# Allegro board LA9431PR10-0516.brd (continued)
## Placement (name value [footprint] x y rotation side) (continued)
PC927  -  [C_0805]  102.62 69.72 90 bottom
PC928  -  [C_0805]  104.36 66.42 90 bottom
PC929  -  [C_0805]  102.62 73.06 90 bottom
PD1  -  [TVNST52302AB0_SOT523-3]  163.31 7 0 top
PD2  -  [TVNST52302AB0_SOT523-3]  160.45 5.51 180 top
PD3  -  [BAS40-05W_SC70-3]  266.42 58.91 0 top
PD4  -  [RB751V-40_SOD323-2]  157.66 9.1 270 top
PD5  -  [DA204U_SOT323-3]  82.44 94.84 270 top
PD6  -  [D_0603]  82.98 81.05 270 top
PD701  -  [RB717F_SOT323-3]  50 17.96 270 top
PD702  -  [RB751V-40_SOD323-2]  53.55 14.2 0 top
PD800  -  [PDS5100H-13_POWERDI5-3]  81.41 13.11 270 bottom
PD806  -  [PDS5100H-13_POWERDI5-3]  173.07 13.49 180 top
PD807  -  [SDMK0340L-7-F_SOD323-2]  155.31 14.57 270 bottom
PD808  -  [PDS5100H-13_POWERDI5-3]  204.18 10.85 90 bottom
PD810  -  [SDMK0340L-7-F_SOD323-2]  135.12 11.84 270 top
PD811  -  [SDMK0340L-7-F_SOD323-2]  175.11 8.01 90 top
PD813  -  [SDMK0340L-7-F_SOD323-2]  192.77 6.66 270 bottom
PD814  -  [SDMK0340L-7-F_SOD323-2]  133.4 9.56 270 top
PD815  -  [RB717F_SOT323-3]  4.19 37.88 180 top
PD816  -  [SDMK0340L-7-F_SOD323-2]  199.95 12.29 90 top
PD818  -  [SDMK0340L-7-F_SOD323-2]  126.78 7.78 0 top
PD819  -  [SDMK0340L-7-F_SOD323-2]  131.96 12.37 180 top
PD820  -  [SDMK0340L-7-F_SOD323-2]  1.88 36.21 90 top
PD821  -  [SDMK0340L-7-F_SOD323-2]  203.44 10.53 0 top
PH500  -  [R_0402]  84.8 69.62 180 bottom
PH501  -  [R_0402]  93.05 64.78 0 top
PJP1  -  [JUMP_43X118]  87.94 81.56 270 bottom
PJP4  -  [JUMP_43X39]  272.69 45.36 180 bottom
PJP5  -  [JUMP_43X39]  43.99 27.56 90 top
PJP6  -  [JUMP_43X39]  33.21 27.98 180 top
PJP7  -  [JUMP_43X39]  10.02 12.34 90 top
PJP8  -  [JUMP_43X39]  197.85 9.64 270 top
PJP9  -  [JUMP_43X39]  94.87 93 180 top
PJP10  -  [JUMP_43X39]  140.88 101.19 0 top
PJP11  -  [JUMP_43X39]  136.38 91.85 180 top
PJP12  -  [JUMP_43X39]  200.83 74.38 270 bottom
PJP13  -  [JUMP_43X39]  195.33 75.91 270 bottom
PJP14  -  [JUMP_43X39]  206.91 69.91 90 bottom
PJP15  -  [JUMP_43X39]  211.14 70.01 90 bottom
PJP16  -  [JUMP_43X39]  189.37 28.89 90 top
PJP17  -  [JUMP_43X39]  190.44 36.41 270 top
PJP18  -  [JUMP_43X39]  185.03 70.18 270 top
PJP19  -  [JUMP_43X39]  186.89 71.09 0 top
PJP20  -  [JUMP_43X39]  201.1 42.14 0 top
PJP21  -  [JUMP_43X39]  200 34.37 90 top
PJP22  -  [JUMP_43X39]  199.71 29.96 0 top
PJP23  -  [JUMP_43X39]  206.55 25.11 180 top
PJP24  -  [JUMP_43X39]  270.89 21.3 270 top
PJP25  -  [JUMP_43X39]  268.2 15.34 90 top
PJP100  -  [JUMP_43X118-S]  182.61 59.21 0 bottom
PJP101  -  [JUMP_43X118]  185.66 63.11 90 top
PJP102  -  [JUMP_43X118]  196.44 65.25 180 top
PJP200  -  [JUMP_43X79]  108.76 6.68 270 top
PJP201  -  [JUMP_43X39]  111.79 8.25 90 top
PJP202  -  [JUMP_43X39]  112.64 5.36 90 top
PJP203  -  [JUMP_43X118]  90.68 13.5 270 top
PJP204  -  [JUMP_43X118]  95.95 13.5 270 top
PJP300  -  [JUMP_43X79]  223.85 72.24 0 top
PJP301  -  [JUMP_43X79]  223.15 80.05 0 bottom
PJP400  -  [JUMP_43X39]  103.89 96.05 180 bottom
PJP401  -  [JUMP_43X39]  95.94 98.41 270 bottom
PJP402  -  [JUMP_43X39]  101.14 98.37 270 bottom
PJP500  -  [JUMP_43X118-S]  74.79 57.76 0 bottom
PJP700  -  [JUMP_43X118-S]  57.83 11.91 0 bottom
PJP701  -  [JUMP_43X39]  56.67 7.63 90 top
PJPDC1  -  [ACES_50299-00501-003_5P]  91.4 92.8 270 bottom
PL1  -  [TAIYO_FBMJ4516HS720NT_2P]  170.39 6.64 180 top
PL2  -  [TAIYO_FBMJ4516HS720NT_2P]  170.39 9.05 180 top
PL3  -  [MURAT_BLM15AG102SN1D_2P]  88.22 86.36 0 top
PL4  -  [TAIYO_FBMJ4516HS720NT_2P]  82.36 81.43 270 bottom
PL100  -  [CYNTE_PCMB053T-1R0MS_2P]  185.28 59.21 180 bottom
PL101  -  [CYNTE_PCMB064T-3R3MS_2P]  198.79 57.73 90 bottom
PL102  -  [CYNTE_PCMB064T-3R3MS_2P]  191.12 57.77 90 bottom
PL200  -  [CYNTE_PCMB064T-3R3MS_2P]  100.5 12.23 0 bottom
PL300  -  [CYNTE_PCMB064T-3R3MS_2P]  229.71 74.59 180 bottom
PL500  -  [CYNTE_PDME064T-R36MS1R405_4P]  97.05 62.31 180 bottom
PL501  -  [L_1812-1806]  73.44 57.75 0 bottom
PL700  -  [CYNTE_PCMB042T-1R0MS_2P]  59.89 11.85 180 bottom
PL701  -  [TOKO_FDVE1040-H-3R3M-P3_2P]  73.76 10.46 180 bottom
PQ1  -  [FDN338P_NL_SOT23-3]  154.81 6.73 0 top
PQ2  -  [FDV301N_NL_SOT23-3]  83.2 85.95 0 top
PQ3  -  [MMST3904-7-F_SOT323-3]  88.82 90.57 180 top
PQ4  -  [SI7121DN-T1-GE3_POWERPAK8-5]  50.81 37.29 0 bottom
PQ6  -  [IMD2AT-108_SC74-6]  55.14 36.25 0 top
PQ100  -  [SI7326DN-T1-E3_PAK1212-8]  202.67 57.17 180 top
PQ101  -  [SI7326DN-T1-E3_PAK1212-8]  189.1 57.68 180 top
PQ102  -  [SI7326DN-T1-E3_PAK1212-8]  197.5 60.72 270 top
PQ103  -  [SI7326DN-T1-E3_PAK1212-8]  193.49 58.29 90 top
PQ200  -  [SI7326DN-T1-E3_PAK1212-8]  107.07 10.62 270 top
PQ201  -  [SI7326DN-T1-E3_PAK1212-8]  105.56 13.61 180 top
PQ300  -  [SI7326DN-T1-E3_PAK1212-8]  228.94 73.93 180 top
PQ301  -  [SI7326DN-T1-E3_PAK1212-8]  232.18 75.54 90 top
PQ700  -  [SI7121DN-T1-GE3_POWERPAK8-5]  53.24 29.97 180 bottom
PQ701  -  [NTR4502PT1G_SOT23-3]  35.46 9.05 270 top
PQ702  -  [NTR4502PT1G_SOT23-3]  34.76 4.99 270 top
PQ703  -  [NTGD4161PT1G_TSOP6]  43.42 11.18 0 top
PQ704  -  [SIR472DP-T1-GE3_POWERPAK8-5]  66.03 11.02 90 top
PQ706  -  [SIR472DP-T1-GE3_POWERPAK8-5]  62.01 9.3 270 top
PQ710  -  [2N7002DW-T-R7_SOT363-6]  97.85 91.06 270 top
PQ712  -  [2N7002DW-T-R7_SOT363-6]  93.72 90.99 180 top
PQ800  -  [SI4835DDY-T1-GE3_SO8]  84.35 14.64 0 bottom
PQ801  -  [FDN338P_NL_SOT23-3]  152.98 13.25 270 bottom
PQ802  -  [2N7002DW-T-R7_SOT363-6]  129.06 9.36 90 top
PQ805  -  [2N7002DW-T-R7_SOT363-6]  128.86 5.89 270 top
PQ806  -  [2N7002DW-T-R7_SOT363-6]  125.16 9.35 180 top
PQ807  -  [2N7002DW-T-R7_SOT363-6]  148.78 12.13 180 bottom
PQ809  -  [SI4835DDY-T1-GE3_SO8]  171.71 14.83 270 bottom
PQ810  -  [FDS6679AZ-G_SO8]  201.23 9.22 180 bottom
PQ811  -  [FDS6679AZ-G_SO8]  158.95 11.02 90 bottom
PQ812  -  [2N7002DW-T-R7_SOT363-6]  176.96 7.26 0 top
PQ813  -  [2N7002DW-T-R7_SOT363-6]  204.71 5.25 270 bottom
PQ814  -  [FDN338P_NL_SOT23-3]  196.02 5.31 90 bottom
PQ815  -  [FDS6679AZ-G_SO8]  179.15 14.83 270 bottom
PQ816  -  [FDV301N_NL_SOT23-3]  194.64 7.86 180 bottom
PQ817  -  [RHU002N06_SOT323-3]  143.24 11.98 270 top
PQ818  -  [RHU002N06_SOT323-3]  140.11 8.33 270 top
PQ819  -  [2N7002DW-T-R7_SOT363-6]  141.24 4.07 90 top
PQ821  -  [2N7002DW-T-R7_SOT363-6]  202.2 17.26 270 top
PQ822  -  [FDN338P_NL_SOT23-3]  202.15 13.36 270 top
PQ823  -  [FDN338P_NL_SOT23-3]  7.42 38.86 180 top
PQ824  -  [2N7002DW-T-R7_SOT363-6]  7.32 42.09 270 top
PQ825  -  [RHU002N06_SOT323-3]  137.01 4.71 90 top
PQ826  -  [FDMC6679AZ_MLP8-5]  192.15 12.08 90 bottom
PQ827  -  [RHU002N06_SOT323-3]  29.55 42.29 90 bottom
PQ828  -  [RHU002N06_SOT323-3]  205.26 19.21 90 top
PQ829  -  [FDN338P_NL_SOT23-3]  2.17 41.45 270 top
PQ830  -  [FDN338P_NL_SOT23-3]  207.05 8.65 270 top
PQ831  -  [RHU002N06_SOT323-3]  211.42 5.87 180 top
PQ832  -  [RHU002N06_SOT323-3]  2.86 40.11 180 bottom
PR1  -  [R_0402]  266.5 55.08 90 top
PR2  -  [R_0402]  155.99 10.64 0 top
PR6  -  [R0402_0OHM]  154.61 13.39 270 top
PR7  -  [R_0402]  81.75 85.18 180 top
PR8  -  [R_0402]  82.98 92.95 270 top
PR9  -  [R_0402]  82.03 92.04 90 top
PR10  -  [R_0402]  85.64 86.97 270 top
PR11  -  [R_0402]  85.62 88.75 270 top
PR12  -  [R_0402]  86.98 87.97 90 top
PR13  -  [R_0402]  89.45 91.72 180 top
PR14  -  [R_0402]  51.23 40.32 0 top
PR15  -  [R_0402]  53.21 18.97 0 top
PR16  -  [R_0805]  51.63 37.55 270 top
PR17  -  [R_0402]  53.02 40.31 90 top
PR18  -  [R_0402]  51.92 41.21 180 top
PR100  -  [R_0402]  199.7 45.06 180 top
PR101  -  [R_0402]  194.81 44.16 90 top
PR102  -  [R_0402]  199.7 44.17 180 top
PR103  -  [R0402_0OHM]  196.58 45.07 270 top
PR104  -  [R_0402]  195.69 44.16 90 top
PR105  -  [R_0402]  200.2 46.08 0 top
PR106  -  [R_0402]  193.92 45.07 270 top
PR107  -  [R_0402]  200.2 47.85 0 top
PR108  -  [R0402_0OHM]  201.12 46.96 180 top
PR109  -  [R_0603]  192.96 50.33 180 top
PR110  -  [R_0603]  202.04 50.2 180 top
PR111  -  [R_1206]  201.08 62.55 180 top
PR112  -  [R_1206]  190.65 62.59 0 top
PR113  -  [R0402_0OHM]  192.95 47.08 180 top
PR114  -  [R_0402]  192.01 47.98 0 top
PR200  -  [R_0603]  111.43 11.75 270 top
PR201  -  [R_0402]  116.7 14.85 270 top
PR202  -  [R_0603]  117.81 13.65 90 top
PR203  -  [R_1206]  101.14 15.34 0 top
PR204  -  [R_0402]  120.43 12.62 180 top
PR205  -  [R_0402]  120.41 6.36 180 top
PR206  -  [R_0402]  120.43 11.73 180 top
PR207  -  [R_0402]  120.43 10.85 180 top
PR208  -  [R0402_0OHM]  120.43 9.96 180 top
PR209  -  [R_0402]  120.4 4.61 180 top
PR210  -  [R0402_0OHM]  120.43 8.18 180 top
PR211  -  [R_0402]  120.43 7.29 180 top
PR300  -  [R_0402]  237.91 71.48 0 top
PR301  -  [R_0603]  236.02 71.09 180 top
PR302  -  [R_0402]  240.86 71.67 180 top
PR303  -  [R_0402]  240.86 72.55 180 top
PR304  -  [R0402_0OHM]  240.86 73.44 180 top
PR305  -  [R_0402]  238.76 76.75 180 top
PR306  -  [R_1206]  231.83 79.32 0 top
PR307  -  [R_0402]  240.86 75.22 180 top
PR308  -  [R_0402]  240.86 76.11 180 top
PR400  -  [R_0402]  103.62 94.54 270 bottom
PR401  -  [R_0402]  103.58 91.85 90 bottom
PR402  -  [R_0402]  94.36 93.85 270 bottom
PR403  -  [R_0402]  93.48 92.06 0 bottom
PR500  -  [R_0402]  91.57 69.71 270 top
PR501  -  [R_0402]  89.13 69.57 0 bottom
PR502  -  [R_0402]  88.77 69.71 270 top
PR503  -  [R_0402]  87.88 69.71 270 top
PR504  -  [R_0402]  87 69.71 270 top
PR505  -  [R_0402]  89.7 68.81 0 top
PR506  -  [R_0402]  90.23 72.06 270 bottom
PR507  -  [R_0402]  89.34 72.06 270 bottom
PR508  -  [R_0402]  88.46 72.06 270 bottom
PR509  -  [R_0402]  87.57 72.06 270 bottom
PR510  -  [R_0402]  92.39 72 270 bottom
PR511  -  [R_0402]  92.46 68.8 90 top
PR512  -  [R_0402]  92.19 63.93 270 top
PR513  -  [R_0402]  87.55 73.7 0 bottom
PR514  -  [R_0402]  93.08 63.93 270 top
PR515  -  [R_0402]  93.97 63.93 270 top
PR516  -  [R_0402]  85.86 75.41 180 top
PR517  -  [R_0603]  79.27 66.76 180 bottom
PR519  -  [R_0603]  84.44 76.48 0 top
PR520  -  [R0402_0OHM]  84.95 72.62 0 top
PR521  -  [R_0402]  91.33 77.57 180 top
PR522  -  [R_1206]  85.61 63.18 270 bottom
PR523  -  [R_0402]  93.1 78.46 180 top
PR526  -  [R_0603]  89.9 78.65 0 top
PR527  -  [R_0402]  88.07 78.66 270 top
PR528  -  [R_0402]  87.19 78.66 270 top
PR529  -  [R_0402]  86.3 78.66 270 top
PR531  -  [R0402_0OHM]  93.37 75.35 90 top
PR532  -  [R0402_0OHM]  94.26 75.35 90 top
PR534  -  [R0402_0OHM]  88.96 77.74 90 top
PR535  -  [R_0402]  93.14 79.46 90 top
PR536  -  [R0402_0OHM]  84.95 71.73 0 top
PR537  -  [R_0402]  84.94 70.85 0 top
PR539  -  [R0402_0OHM]  84.95 74.52 0 top
PR540  -  [R_0402]  84.95 73.63 0 top
PR700  -  [R_1206_4P-D]  52.96 23.7 90 bottom
PR701  -  [R0402_0OHM]  49.99 29.12 90 bottom
PR702  -  [R0402_0OHM]  39.32 5.64 270 top
PR703  -  [R_0402]  45.62 8.7 270 top
PR704  -  [R_0402]  46.48 7.8 0 top
PR705  -  [R_0402]  46.48 8.69 0 top
PR706  -  [R_0402]  41.1 5.57 180 top
PR707  -  [R_0402]  44.49 9.75 0 top
PR708  -  [R_0805]  46.95 15.72 0 top
PR709  -  [R0402_0OHM]  41.1 4.58 180 top
PR710  -  [R0402_0OHM]  43.63 3.83 180 top
PR711  -  [R_0402]  54.75 15.44 90 top
PR713  -  [R_0402]  49.7 4.84 270 top
PR714  -  [R_0402]  51.42 4.81 270 top
PR715  -  [R_0603]  53.63 11.45 90 top
PR716  -  [R_1206_4P-D]  77.74 15.3 270 bottom
PR717  -  [R0402_0OHM]  47.54 3.47 0 top
PR718  -  [R0402_0OHM]  58.73 4.89 270 top
PR719  -  [R0402_0OHM]  57.81 4.86 270 top
PR722  -  [R_0402]  56.91 3.94 90 top
PR724  -  [R_1206]  60.2 6.31 270 top
PR725  -  [R0402_0OHM]  47.61 4.55 90 top
PR726  -  [R_0402]  55.82 3.91 180 top
PR727  -  [R_0402]  92.37 83.76 270 top
PR728  -  [R0402_0OHM]  100.93 91.3 0 top
PR729  -  [R_0402]  93.38 85.67 90 top
PR730  -  [R_0402]  95.12 88.56 270 top
PR732  -  [R_0402]  97.47 85.65 180 top
PR734  -  [R_0402]  94.26 87.48 180 top
PR735  -  [R_0402]  95.19 86.61 270 top
PR736  -  [R_0402]  95.06 83.74 270 top
PR737  -  [R_0402]  95.91 81.9 0 top
PR738  -  [R_0402]  96.01 80.59 90 bottom
PR739  -  [R_0402]  95.12 80.59 90 bottom
PR740  -  [R_0402]  99.73 88.72 270 top
PR741  -  [R0402_0OHM]  94.23 81.51 270 bottom
PR742  -  [R_0402]  95.94 82.83 90 top
PR743  -  [R_0402]  97.79 81.51 270 bottom
PR744  -  [R_0402]  93.35 81.51 270 bottom
PR745  -  [R_1206]  48.31 13.37 0 top
PR746  -  [R_0402]  50.32 6.12 0 bottom
PR747  -  [R_0402]  48.5 5.44 270 top
PR748  -  [R_0402]  41.97 7.14 0 top
PR749  -  [R_0402]  41.07 6.49 90 top
PR750  -  [R0402_0OHM]  55.82 4.8 180 top
PR751  -  [R_0402]  53.16 3.68 0 top
PR801  -  [R_0402]  127.18 4.98 90 top
PR802  -  [R_0402]  151.87 10.77 0 bottom
PR804  -  [R_0402]  150.94 10.77 180 bottom
PR807  -  [R_0402]  132.04 6.98 180 top
PR808  -  [R_0402]  147.23 10.71 0 bottom
PR810  -  [R_0402]  122.73 9.23 90 top
PR811  -  [R0402_0OHM]  197.03 7.73 0 bottom
PR812  -  [R0402_0OHM]  122.73 11.99 270 top
PR813  -  [R_0402]  177.5 11.68 90 top
PR814  -  [R_0402]  198.63 15.02 270 top
PR815  -  [R_0402]  177.51 10.77 180 top
PR816  -  [R_0402]  178.61 5.92 180 top
PR817  -  [R_0402]  167.18 14.05 90 top
PR818  -  [R_0402]  193.12 10.49 180 top
PR819  -  [R_0402]  143.09 10.27 270 top
PR820  -  [R0402_0OHM]  138.52 12.61 0 top
PR821  -  [R_0603]  156.77 13.37 90 bottom
PR822  -  [R_0402]  193.12 9.61 180 top
PR823  -  [R_0402]  138.86 8.29 270 top
PR824  -  [R_0402]  141.52 6.59 180 top
PR825  -  [R0402_0OHM]  138.13 9.23 0 top
PR826  -  [R_0402]  199.81 5.93 0 bottom
PR827  -  [R_0402]  199.82 4.78 270 bottom
PR828  -  [R_0402]  2.41 42.8 0 bottom
PR829  -  [R_0402]  209.6 2.82 180 top
PR830  -  [R_0402]  5.44 40.94 180 bottom
PR831  -  [R0402_0OHM]  1.44 27.09 0 top
PR832  -  [R0402_0OHM]  1.44 27.98 0 top
PR833  -  [R0402_0OHM]  1.44 25.5 0 top
PR834  -  [R0402_0OHM]  147.87 14.13 0 top
PR835  -  [R_0805]  2.6 21.45 90 top
PR836  -  [R_0402]  208.13 11.07 0 top
PR837  -  [R_0402]  211.76 7.04 180 top
PR838  -  [R0402_0OHM]  2.25 31.28 270 top
PR839  -  [R_0402]  205.98 13.06 270 top
PR840  -  [R_0402]  205.98 13.98 90 top
PR841  -  [R0402_0OHM]  1.44 29.25 0 top
PR843  -  [R0402_0OHM]  2.86 32.61 180 top
PR844  -  [R_0402]  4.52 38.96 180 top
PR846  -  [R_0402]  10.15 22.85 270 top
PR847  -  [R0402_0OHM]  6.4 22.19 90 top
PR848  -  [R_0402]  200.71 3.77 90 bottom
PR849  -  [R_0402]  179.93 5.88 0 top
PR850  -  [R0402_0OHM]  2.86 33.5 180 top
PR851  -  [R_0402]  206.17 16.74 180 top
PR852  -  [R0402_0OHM]  146.37 11.29 0 top
PR853  -  [R0402_0OHM]  201.6 3.76 90 bottom
PR854  -  [R0402_0OHM]  7.29 22.19 90 top
PR855  -  [R0402_0OHM]  5.19 33.24 90 top
PR856  -  [R_0402]  28.37 41.13 90 bottom
PR857  -  [R0402_0OHM]  6.97 33.24 90 top
PR858  -  [R_0402]  6.08 34.15 270 top
PR859  -  [R0402_0OHM]  8.18 22.19 90 top
PR860  -  [R0402_0OHM]  7.85 33.13 90 top
PR861  -  [R0402_0OHM]  202.53 19.14 90 top
PR862  -  [R0402_0OHM]  9.07 22.19 90 top
PR863  -  [R0402_0OHM]  8.74 33.13 90 top
PR864  -  [R_0402]  138.15 6.52 270 top
PR866  -  [R0402_0OHM]  12.76 29.76 180 top
PR868  -  [R0402_0OHM]  11.85 30.64 0 top
PR869  -  [R_0402]  8.89 35.03 180 top
PR870  -  [R_0402]  6.46 41.87 90 bottom
PR872  -  [R0402_0OHM]  133.83 4.15 90 top
PR874  -  [R_0402]  11.85 28.87 0 top
PR875  -  [R_0402]  10.38 42.75 270 top
PR877  -  [R0402_0OHM]  11.85 27.98 0 top
PR894  -  [R_0402]  4.92 40.04 0 bottom
PR895  -  [R0402_0OHM]  4.52 41.83 0 bottom
PRP2  -  [RP_0804_8P4R]  160.16 12.66 270 top
PU2  -  [LM393DR_SO8]  93.73 88.71 0 bottom
PU3  -  [TC7SH08FU_SSOP5]  102.99 88.97 90 top
PU11  -  [RT8207MZQW_WQFN20_3X3]  115.01 8.89 0 top
PU100  -  [TPS51225CRUKR_QFN20_3X3]  196.04 47.7 0 top
PU111  -  [TS5A63157DCKR_SC70-6]  79.6 93.97 0 top
PU300  -  [TPS51218DSCR_SON10_3X3]  238.62 73.08 90 top
PU400  -  [APL5915KAI-TRL_SO8]  95.96 92.13 90 bottom
PU500  -  [TPS51622RSM_QFN32_4X4]  87.81 74.84 270 top
PU501  -  [CSD97374CQ4M_SON8_3P5X4P5-S]  84.22 67.92 270 bottom
PU700  -  [BQ24715RGRR_QFN20_3P5X3P5]  50.84 8.91 270 top
PU703  -  [INA199A2DCKR_SC70-6]  45.17 4.82 90 top
PU800  -  [CD3301RHHR_QFN36_6X6]  4.78 25.2 0 top
PU801  -  [TC7SH08FU_SSOP5]  131.9 10.89 180 top
PU804  -  [TC7SH08FU_SSOP5]  123.82 12.18 270 top
PU805  -  [TC7SH08FU_SSOP5]  141.72 12.16 180 top
PU806  -  [TC7SH08FU_SSOP5]  139.23 10.31 90 top
PU807  -  [TC7SH08FU_SSOP5]  136.97 6.63 90 top
PU808  -  [TC7SH08FU_SSOP5]  209.6 5.93 180 top
Q1  -  [LP2301ALT1G_SOT23-3]  142.84 103.35 270 top
Q2  -  [FDC654P-G_SSOT-6]  65.52 68.9 0 bottom
Q3  -  [LP2301ALT1G_SOT23-3]  91.77 94.4 90 top
Q4  -  [L2N7002WT1G_SC-70-3]  72.38 68.81 0 top
Q5  -  [DMN66D0LDW-7_SOT363-6]  33.5 24.34 180 top
Q6  -  [BSS138W-7-F_SOT323-3]  179.76 89.45 270 bottom
Q7  -  [L2N7002WT1G_SC-70-3]  53.77 77.12 0 top
Q9  -  [L2N7002WT1G_SC-70-3]  13.07 21.5 180 top
Q10  -  [BSS138W-7-F_SOT323-3]  210.74 88.5 0 bottom
Q11  -  [MMBT3904WT1G_SC70-3]  131.57 70.77 0 top
Q12  -  [MMST3904-7-F_SOT323-3]  33.96 20.36 270 top
Q13  -  [MMBT3904WT1G_SC70-3]  126.02 18.54 0 top
Q14  -  [MMBT3904WT1G_SC70-3]  97.01 56.55 270 bottom
Q15  -  [PDTA114EU_SC70-3]  204.11 93.52 90 bottom
Q16  -  [PDTA114EU_SC70-3]  204.11 95.94 90 bottom
Q17  -  [DMN66D0LDW-7_SOT363-6]  148.19 99.48 90 top
Q20  -  [DMN66D0LDW-7_SOT363-6]  278.51 26.65 180 top
Q21  -  [DMN66D0LDW-7_SOT363-6]  281.75 24.27 90 top
Q22  -  [DMN66D0LDW-7_SOT363-6]  208.09 27.23 270 top
Q23  -  [DMN66D0LDW-7_SOT363-6]  110.97 109.26 0 top
Q24  -  [DMN66D0LDW-7_SOT363-6]  199.1 93.32 0 top
Q25  -  [DMN66D0LDW-7_SOT363-6]  200.22 93.32 180 bottom
Q26  -  [PDTA114EU_SC70-3]  195.97 91.73 270 bottom
Q28  -  [DMN66D0LDW-7_SOT363-6]  231.3 108.11 0 bottom
Q29  -  [L2N7002WT1G_SC-70-3]  187.96 97.09 270 top
Q30  -  [DMN66D0LDW-7_SOT363-6]  205.84 40.87 0 top
Q31  -  [BSS138W-7-F_SOT323-3]  231.57 89.7 270 bottom
Q32  -  [DMN66D0LDW-7_SOT363-6]  232.32 94.93 180 top
Q33  -  [DMN66D0LDW-7_SOT363-6]  234.76 96.15 180 top
Q120  -  [DMN66D0LDW-7_SOT363-6]  203.24 99.94 270 bottom
Q121  -  [L2N7002WT1G_SC-70-3]  202.23 97.19 270 top
Q123  -  [DMN66D0LDW-7_SOT363-6]  267.56 24.36 0 top
Q124  -  [DMN66D0LDW-7_SOT363-6]  160.04 92.03 180 top
Q125  -  [SI3456DDV-T1-GE3_TSOP6]  151.04 91.77 90 top
QC1  -  [DMN66D0LDW-7_SOT363-6]  163.23 70.46 0 top
QD1  -  [BSS138-G_SOT23-3]  121.62 31.88 90 top
R1  -  [R_0402]  168.92 74.04 270 bottom
R2  -  [R_0402]  174.28 74.03 270 bottom
R3  -  [R_0402]  170.31 82.84 180 bottom
R4  -  [R_0402]  163.69 83.27 90 bottom
R5  -  [R_0402]  176.1 75.96 270 bottom
R6  -  [R_0402]  169.79 73.11 90 bottom
R7  -  [R_0402]  179.25 79.11 270 bottom
R8  -  [R_0402]  166.12 75.03 180 bottom
R9  -  [R_0402]  176.19 81.99 270 bottom
R10  -  [R_0402]  170.6 81.72 0 bottom
R11  -  [R_0402]  175.22 82.65 270 bottom
R12  -  [R_0402]  174.37 81.76 180 bottom
R13  -  [R_0402]  177.41 78.19 90 bottom
R14  -  [R_0402]  164.52 68.69 270 bottom
R15  -  [R_0402]  165.2 72.75 0 bottom
R16  -  [R_0402]  175.23 73.1 90 bottom
R17  -  [R_0402]  164.5 69.63 0 bottom
R18  -  [R_0402]  178.3 78.19 90 bottom
R19  -  [R_0402]  166.94 74.04 0 bottom
R20  -  [R_0402]  179.25 76.42 90 bottom
R21  -  [R_0402]  176.19 79.31 90 bottom
R22  -  [R_0402]  164.64 82.92 0 bottom
R23  -  [R_0402]  167.86 73.15 180 bottom
R24  -  [R_0402]  110.99 91.05 270 bottom
R25  -  [R_0402]  247.75 71.97 270 top
R26  -  [R_0402]  194.6 40.4 0 top
R27  -  [R_0402]  250.43 28.66 90 top
R28  -  [R_0402]  127.75 28.52 90 top
R29  -  [R_0402]  99.2 19.98 180 top
R30  -  [R_0402]  99.2 19.09 180 top
R31  -  [R_0402]  176.31 17.81 270 top
R32  -  [R_0402]  128.64 28.54 90 top
R33  -  [R_0402]  177.45 17.81 270 top
R35  -  [R_0402]  31.1 24.43 270 top
R36  -  [R_0402]  34.53 23.29 270 top
R37  -  [R0402_0OHM]  252.4 9.13 270 top
R38  -  [R_0402]  254.47 9.09 270 top
R39  -  [R_0402]  279.88 33.25 0 top
R40  -  [R_0402]  194.11 88.67 90 top
R41  -  [R_0402]  164.64 82.02 0 bottom
R42  -  [R_0402]  195.95 88.67 90 top
R43  -  [R_0402]  173.38 74.03 270 bottom
R44  -  [R_0402]  203.48 78.14 0 top
R45  -  [R_0402]  179.25 74.64 90 bottom
R46  -  [R_0402]  200.65 89.12 90 top
R47  -  [R_0402]  203.48 79.03 0 top
R48  -  [R_0402]  172.49 74.03 270 bottom
R49  -  [R_0402]  201.54 89.12 90 top
R50  -  [R_0402]  29.54 38.52 180 top
R51  -  [R_0402]  14.38 25.39 90 top
R52  -  [R_0402]  187.96 87.79 180 top
R53  -  [R_0402]  202.92 74.46 0 top
R54  -  [R_0402]  203.48 75.35 0 top
R56  -  [R_0402]  180.33 81.71 270 bottom
R57  -  [R_0402]  178.22 82.59 0 bottom
R58  -  [R_0402]  171.55 74.03 270 bottom
R59  -  [R_0402]  170.66 74.03 270 bottom
R60  -  [R_0402]  210.68 85.31 90 bottom
R63  -  [R_0402]  189.15 73.3 90 top
R64  -  [R_0402]  192.68 86.64 0 bottom
R65  -  [R_0402]  191.87 78.33 0 bottom
R66  -  [R_0402]  187.06 76.12 270 top
R67  -  [R_0402]  236.91 90.28 270 top
R69  -  [R_0402]  191.31 88.73 90 top
R70  -  [R_0402]  203.49 77.18 0 top
R72  -  [R_0402]  203.49 76.29 0 top
R73  -  [R0402_0OHM]  212.1 81.88 90 top
R74  -  [R_0402]  190.09 73.25 0 top
R75  -  [R0402_0OHM]  210.25 81.85 90 top
R76  -  [R0402_0OHM]  209.36 78.4 90 top
R77  -  [R0402_0OHM]  213.91 79.98 0 top
R81  -  [R0402_0OHM]  213.91 80.87 0 top
R84  -  [R0402_0OHM]  207.56 78.36 90 top
R85  -  [R_0402]  193.95 74.38 270 top
R88  -  [R0402_0OHM]  206.67 78.36 90 top
R91  -  [R_0402]  198.62 89.18 90 top
R92  -  [R_0402]  199.63 89.18 90 top
R94  -  [R_0402]  146.67 102.73 270 top
R95  -  [R_0402]  59.18 79.48 180 top
R96  -  [R_0402]  58.9 83.79 0 top
R97  -  [R_0402]  70.61 67.86 180 top
R99  -  [R_0402]  69.7 68.81 0 top
R100  -  [R_0402-S]  68.16 70.91 110 bottom
R101  -  [R_0402-S]  69.26 71.27 110 bottom
R102  -  [R_0402]  81.97 96.11 90 top
R104  -  [R_0402]  54.76 68.17 90 top
R106  -  [R0402_0OHM]  83.79 96.75 180 top
R107  -  [R0402_0OHM]  187.12 78.03 270 top
R108  -  [R_0402]  66.29 73.74 0 bottom
R120  -  [R_0402]  114.86 109.09 270 top
R121  -  [R_0402]  113.27 95.08 90 bottom
R122  -  [R_0402]  125.78 27.9 90 top
R123  -  [R_0402]  124.89 27.9 90 top
R129  -  [R0402_0OHM]  203.15 22.54 90 top
R130  -  [R0805_0OHM]  266.6 40.13 270 top
R131  -  [R0402_0OHM]  190.32 41.31 270 top
R136  -  [R_0402]  274.13 27.61 90 top
R137  -  [R_0402]  280.8 29.69 180 top
R139  -  [R_0402]  280.8 30.58 180 top
R140  -  [R0603_0OHM]  269.8 15.15 0 top
R142  -  [R_0402]  280.8 31.47 180 top
R143  -  [R0402_0OHM]  280.8 32.36 180 top
R144  -  [R0402_0OHM]  278.64 40.21 270 top
R145  -  [R0402_0OHM]  242.43 74.09 0 top
R147  -  [R_0402]  274.22 23.42 180 top
R148  -  [R_0402]  272.3 28.51 270 top
R149  -  [R_0402]  273.25 28.51 270 top
R150  -  [R_0402]  266.9 29.69 0 top
R151  -  [R_0402]  274.22 24.32 180 top
R152  -  [R_0402]  277.8 28.63 270 top
R153  -  [R_0402]  275.2 26.01 0 top
R154  -  [R0402_0OHM]  266.19 22.4 270 top
R155  -  [R_0402]  45.57 29.51 270 top
R156  -  [R_0402]  278.69 28.63 270 top
R157  -  [R_0402]  279.88 28.74 0 top
R158  -  [R_0402]  282.37 21.5 90 top
R159  -  [R_0402]  281.47 21.5 90 top
R160  -  [R_0402]  155.68 76.83 180 bottom
R161  -  [R_0402]  168 82.84 0 top
R162  -  [R_0402]  272.44 39.71 90 top
R163  -  [R_0402]  237.68 85.89 180 top
R164  -  [R_0402]  166.87 89.12 90 bottom
R165  -  [R_0402]  237.68 87.86 180 top
R166  -  [R_0402]  273.33 39.71 90 top
R167  -  [R_0402]  237.8 89.37 90 top
R168  -  [R_0402]  271.62 88.61 90 top
R169  -  [R0402_0OHM]  256.79 73.13 180 top
R170  -  [R_0402]  270.52 28.57 270 top
R171  -  [R_0402]  245.97 76.24 0 top
R172  -  [R_0402]  245.97 75.29 0 top
R173  -  [R_0402]  261.86 72.31 270 top
R174  -  [R0402_0OHM]  245.97 78.97 0 top
R175  -  [R0402_0OHM]  259.21 76.24 180 top
R176  -  [R_0402]  258.29 74.4 0 top
R177  -  [R0402_0OHM]  245.97 77.19 0 top
R178  -  [R_0402]  259.21 73.51 180 top
R179  -  [R0402_0OHM]  259.21 75.29 180 top
R180  -  [R0402_0OHM]  263.83 71.4 90 top
R181  -  [R0603_0OHM]  259.77 83.16 270 top
R182  -  [R_0402]  262.88 71.4 90 top
R183  -  [R0402_0OHM]  258.31 77.11 90 top
R184  -  [R_0402]  246.89 78.08 180 top
R185  -  [R_0402]  258.29 80.75 0 top
R186  -  [R_0402]  267.2 32.19 180 top
R187  -  [R_0402]  276.36 39.17 90 top
R190  -  [R_0402]  181.79 7.99 0 top
R191  -  [R_0402]  181.79 8.88 0 top
R193  -  [R0402_0OHM]  35.24 39.33 270 top
R194  -  [R_0402]  275.2 23.28 0 top
R195  -  [R_0402]  189.98 9 270 top
R196  -  [R0402_0OHM]  198.12 38.58 180 top
R197  -  [R_0402]  276.14 40.93 0 top
R198  -  [R_0402]  108.36 83.63 90 bottom
R202  -  [R_0402]  268.39 27.56 180 top
R205  -  [R_0402]  260.4 26.15 270 top
R206  -  [R_0402]  258.31 78.89 90 top
R207  -  [R_0402]  193.15 89.65 270 top
R211  -  [R_0402]  254.5 15.52 270 top
R212  -  [R_0402]  251.8 20.14 0 top
R213  -  [R_0402]  267.78 22.91 0 top
R214  -  [R_0402]  252.72 21.03 180 top
R215  -  [R_0402]  209.26 18.12 90 top
R216  -  [R_0402]  205.68 48.22 0 top
R217  -  [R_0402]  205.68 50.89 0 top
R218  -  [R_0402]  206.59 49.11 180 top
R219  -  [R_0402]  206.59 50 180 top
R220  -  [R0402_0OHM]  267.78 22.01 0 top
R222  -  [R_0402]  209.27 13.63 0 top
R223  -  [R0402_0OHM]  208.36 29.46 0 bottom
R224  -  [R_0402]  209.83 23.7 90 top
R225  -  [R_0402]  207.95 28.94 0 top
R226  -  [R_0402]  206.9 44.84 270 top
R227  -  [R_0402]  207.14 27.56 270 top
R228  -  [R_0402]  211.09 26.01 90 top
R229  -  [R_0402]  205.63 39.7 0 top
R230  -  [R_0402]  263.37 20.74 0 top
R231  -  [R0402_0OHM]  269.11 13.03 270 top
R235  -  [R_0402-S]  205.02 95.61 0 top
R236  -  [R_0402-S]  205.02 94.4 0 top
R237  -  [R_0402-S]  205.02 93.45 0 top
R238  -  [R_0402-S]  202.67 90.53 0 bottom
R239  -  [R_0402-S]  205.02 92.3 0 top
R240  -  [R_0402-S]  202.67 89.64 0 bottom
R241  -  [R0402_0OHM]  54.04 74.08 180 top
R242  -  [R0402_0OHM]  49.66 73.23 90 top
R243  -  [R_0402]  53.76 78.33 0 top
R244  -  [R_0402]  71.49 87.55 270 top
R246  -  [R_0402-S]  75.93 89.12 90 top
R247  -  [R_0402-S]  77.08 89.12 90 top
R248  -  [R_0402-S]  77.97 89.12 90 top
R249  -  [R_0402-S]  73.14 89.12 90 top
R250  -  [R_0402-S]  79.17 89.12 90 top
R251  -  [R_0402-S]  74.28 89.12 90 top
R252  -  [R_0402]  115.1 95.12 90 bottom
R253  -  [R_0402]  115.99 95.12 90 bottom
R254  -  [R_0402]  115.99 96.03 270 top
R255  -  [R_0402]  116.88 95.12 90 bottom
R256  -  [R_0402]  116.88 96.03 270 top
R257  -  [R_0402]  117.77 95.12 90 bottom
R258  -  [R_0402]  119.54 96.03 270 top
R259  -  [R_0402]  114.21 95.12 90 bottom
R260  -  [R_0402]  114.21 96.03 270 top
R261  -  [R_0402]  115.1 96.03 270 top
R262  -  [R_0402]  117.77 96.03 270 top
R263  -  [R_0402]  118.66 95.12 90 bottom
R264  -  [R_0402]  118.66 96.03 270 top
R265  -  [R_0402]  119.54 95.12 90 bottom
R266  -  [R_0402]  120.43 95.12 90 bottom
R267  -  [R_0402]  120.43 96.03 270 top
R268  -  [R_0402]  123.74 96.92 270 bottom
R269  -  [R0402_0OHM]  124.58 95.62 0 top
R270  -  [R0402_0OHM]  124.58 96.63 0 top
R271  -  [R_0402]  123.38 108.11 180 top
R272  -  [R_0402]  147.96 109 180 top
R273  -  [R_0402]  145.39 97.19 0 bottom
R274  -  [R_0402]  243.12 94.72 0 top
R275  -  [R_0402]  261.54 88.85 90 top
R276  -  [R_0402]  262.5 88.85 90 top
R277  -  [R_0402]  248.37 94.39 270 top
R278  -  [R_0402]  249.64 94.39 270 top
R279  -  [R_0402]  256.03 94.32 270 top
R280  -  [R_0402]  257.3 94.32 270 top
R281  -  [R_0402]  17.45 42.66 270 top
R282  -  [R_0402]  25.26 42.91 270 top
R284  -  [R_0402]  17.39 26.25 90 top
R285  -  [R_0402]  25.26 42 90 bottom
R287  -  [R_0402]  15.55 26.25 90 top
R288  -  [R_0402]  23.99 42.91 270 top
R289  -  [R_0402]  16.43 26.25 90 top
R291  -  [R_0402]  15.46 42.46 270 bottom
R292  -  [R_0402]  10.01 37.01 270 top
R293  -  [R_0402]  29.46 27.34 180 top
R295  -  [R_0402]  19.74 42.66 270 top
R296  -  [R_0402]  29.46 33.76 180 top
R297  -  [R0402_0OHM]  267.97 13.03 270 top
R298  -  [R_0402]  22.28 26.25 90 top
R299  -  [R_0402]  29.46 31.98 180 top
R300  -  [R_0402]  29.46 32.87 180 top
R301  -  [R_0402]  32.74 30.26 0 top
R303  -  [R_0402]  21.32 26.25 90 top
R304  -  [R_0402]  23.23 26.25 90 top
R305  -  [R_0402]  29.46 29.18 180 top
R306  -  [R0402_0OHM]  261.25 11.67 0 top
R307  -  [R_0402]  29.53 37.57 180 top
R309  -  [R_0402]  22.47 42.72 270 top
R310  -  [R_0402]  17.41 42.49 270 bottom
R311  -  [R_0402]  212.09 83.72 0 top
R312  -  [R_0402]  210.24 83.72 0 top
R313  -  [R_0402]  18.34 42.66 270 top
R315  -  [R0402_0OHM]  261.25 10.53 0 top
R317  -  [R_0402]  10.06 34.96 0 top
R319  -  [R0402_0OHM]  29.46 28.3 180 top
R320  -  [R_0402]  10.97 34.06 180 top
R321  -  [R_0402]  28.55 30.96 0 top
R322  -  [R_0402]  10.87 39.62 180 top
R324  -  [R_0402]  28.61 36.55 0 top
R325  -  [R_0402]  11.99 40.22 270 top
R326  -  [R_0402]  19.93 27.16 270 top
R327  -  [R_0402]  13.28 5.31 0 top
R328  -  [R_0402]  11.81 5.31 180 top
R329  -  [R_0402]  14.2 6.26 180 top
R330  -  [R_0402]  14.48 3.47 180 top
R331  -  [R_0402]  244.02 71.59 90 top
R332  -  [R0402_0OHM]  13.63 15.21 0 top
R333  -  [R0402_0OHM]  261.25 8.43 0 top
R334  -  [R0402_0OHM]  14.22 20.36 180 top
R335  -  [R_0402]  15.8 23.1 270 top
R336  -  [R0402_0OHM]  33.96 12.41 90 top
R337  -  [R0402_0OHM]  261.25 9.58 0 top
R338  -  [R_0402]  32.51 6.91 180 top
R339  -  [R_0402]  16.42 15.67 0 top
R340  -  [R_0402]  35.48 24.47 90 top
R341  -  [R0402_0OHM]  263.37 23.6 0 top
R342  -  [R_0402]  14.85 23.1 270 top
R343  -  [R_0402]  23.29 24.31 270 top
R344  -  [R_0402]  35.74 13.32 270 top
R345  -  [R_0402]  13.63 17.12 0 top
R346  -  [R_0402]  15.53 7.98 0 top
R347  -  [R_0402]  15.53 8.86 0 top
R348  -  [R_0402]  21.13 23.1 270 top
R349  -  [R_0402]  11 20.22 270 top
R350  -  [R_0402]  34.53 24.47 90 top
R351  -  [R_0402]  209.35 80.34 180 top
R352  -  [R_0402]  15.8 4.37 270 top
R353  -  [R_0402]  28.69 23.16 270 top
R354  -  [R_0402]  26.85 23.16 270 top
R355  -  [R_0402]  37.45 23.29 270 top
R356  -  [R_0402]  25.96 23.16 270 top
R357  -  [R_0402]  36.5 23.29 270 top
R358  -  [R_0402]  16.69 4.37 270 top
R359  -  [R_0402]  20.94 6.37 90 top
R360  -  [R_0402]  13.56 18.2 0 top
R361  -  [R_0402]  20.05 4.75 270 top
R362  -  [R_0402]  32.51 6.03 180 top
R363  -  [R_0402]  27.8 23.16 270 top
R364  -  [R_0402]  21.01 4.75 270 top
R365  -  [R_0402]  19.99 6.37 90 top
R366  -  [R_0402]  25.07 23.16 270 top
R367  -  [R_0402]  16.69 22.19 90 top
R368  -  [R_0402]  32.89 14.2 180 top
R369  -  [R_0402]  32.89 11.53 180 top
R370  -  [R_0402]  17.58 22.19 90 top
R371  -  [R_0402]  32.89 15.09 180 top
R372  -  [R_0402]  34.26 14.2 0 top
R373  -  [R_0402]  39.29 23.29 270 top
R374  -  [R0402_0OHM]  19.37 23.09 180 top
R375  -  [R_0402]  20.24 22.19 90 top
R376  -  [R_0402]  36.75 12.41 90 top
R377  -  [R_0402]  38.34 23.29 270 top
R378  -  [R0402_0OHM]  16.43 10.01 90 top
R379  -  [R0402_0OHM]  13.63 16.17 0 top
R380  -  [R_0402]  11.09 18.45 0 top
R381  -  [R_0402]  17.34 12.69 180 top
R382  -  [R_0402]  31.99 17.27 0 top
R383  -  [R_0402]  35.18 15.98 180 top
R384  -  [R_0402]  12 17.5 180 top
R385  -  [R_0402]  6.96 7.57 90 top
R386  -  [R_0402]  23.86 4.75 270 top
R387  -  [R_0402]  31.6 5.14 0 top
R388  -  [R_0402]  5.88 7.57 90 top
R391  -  [R_0402]  7.98 7.57 90 top
R392  -  [R_0402]  25.91 3.91 180 top
R393  -  [R_0402]  11.71 8.14 0 top
R394  -  [R_0402]  31.98 8.79 0 top
R397  -  [R_0402]  9.88 7.57 90 top
R398  -  [R_0402]  8.93 7.57 90 top
R399  -  [R_0402]  11.71 9.03 0 top
R400  -  [R0402_0OHM]  5.89 6.67 270 top
R401  -  [R_0402]  22.34 23.1 270 top
R402  -  [R_0402]  32.91 19.91 180 top
R403  -  [R_0402]  34.52 18.64 0 top
R404  -  [R_0402]  192.76 18.26 0 top
R405  -  [R_0402]  190.96 18.15 180 top
R408  -  [R_0402]  35.18 15.09 180 top
R410  -  [R0402_0OHM]  263.37 22.64 0 top
R411  -  [R_0402]  37.12 19.53 0 top
R413  -  [R0402_0OHM]  39.99 9.64 270 top
R414  -  [R_0402]  41.64 13.87 90 top
R416  -  [R0402_0OHM]  207.3 76.89 270 bottom
R417  -  [R_0402]  211.4 75.95 270 bottom
R418  -  [R0402_0OHM]  210.5 75.93 270 bottom
R420  -  [R0402_0OHM]  161.15 90.23 90 top
R421  -  [R_0402]  196.1 33.2 180 top
R422  -  [R0402_0OHM]  196.1 32.31 180 top
R423  -  [R_0402]  196.1 34.09 180 top
R424  -  [R0402_0OHM]  196.1 34.98 180 top
R425  -  [R_0402]  189.41 66.6 270 bottom
R426  -  [R0402_0OHM]  190.3 66.6 270 bottom
R427  -  [R_0402]  113.77 110.53 0 top
R428  -  [R_0402]  195.28 94.74 180 top
R429  -  [R_0402]  109.98 111.42 180 top
R430  -  [R_0402]  205.16 94.77 90 bottom
R431  -  [R_0402]  109.98 110.46 180 top
R432  -  [R_0402]  196.19 94.74 0 top
R433  -  [R_0402]  113.77 111.42 0 top
R434  -  [R_0402]  224.52 97.56 0 top
R435  -  [R_0402]  204.23 98.21 180 top
R436  -  [R_0402]  231.7 109.82 90 bottom
R438  -  [R_0402]  194.88 91.73 180 bottom
R439  -  [R_0402]  196.08 31.41 180 top
R440  -  [R_0402]  40.69 14.78 270 top
R441  -  [R0402_0OHM]  192.76 17.37 0 top
R442  -  [R_0402]  161.05 89.08 180 top
R443  -  [R0402_0OHM]  251.38 29.58 270 top
R444  -  [R0402_0OHM]  190.97 17.26 180 top
R445  -  [R_0402]  159.78 93.1 180 top
R447  -  [R_0402]  148.02 88.79 0 top
R449  -  [R_0402]  189.2 17.22 270 top
R450  -  [R_0402]  188.25 18.2 0 top
R451  -  [R_0402]  21.9 6.37 90 top
R452  -  [R_0402]  23.8 6.37 90 top
R453  -  [R_0402]  22.91 4.75 270 top
R460  -  [R_0402]  184.26 96.93 90 top
R462  -  [R_0402]  196.33 96.54 90 top
R463  -  [R_0402]  197.22 96.54 90 top
R464  -  [R_0402]  193.92 96.54 90 top
R465  -  [R_0402]  189.15 96.54 90 top
R466  -  [R_0402]  194.81 96.54 90 top
R467  -  [R_0402]  191.57 96.54 90 top
R468  -  [R_0402]  190.04 96.54 90 top
R469  -  [R_0402]  192.46 96.54 90 top
R470  -  [R_0402]  203.25 97.56 180 bottom
R471  -  [R_0402]  204.52 100.58 90 bottom
R472  -  [R0402_0OHM]  201.22 96.42 90 bottom
R473  -  [R_0402]  199.14 98.09 180 top
R474  -  [R_0402]  203.3 97.23 0 top
R475  -  [R_0402]  199.14 96.76 180 top
R480  -  [R_0402]  271.58 48.79 90 bottom
R481  -  [R_0402]  274.63 49.77 270 bottom
R482  -  [R_0402-S]  265.16 76.71 90 top
R483  -  [R_0402-S]  264.02 76.71 90 top
R484  -  [R_0402-S]  266.06 85.9 315 top
R485  -  [R_0402-S]  265.25 85.09 315 top
R486  -  [R_0402-S]  264.57 84.41 315 top
R487  -  [R_0402-S]  263.77 83.61 315 top
R490  -  [R0402_0OHM]  18.22 7.66 180 top
R491  -  [R0402_0OHM]  275.32 47.31 180 bottom
R492  -  [R0402_0OHM]  272.33 50.9 180 top
R493  -  [R_0402]  249.21 16.71 180 top
RC1  -  [R_0402]  165.53 56.46 270 bottom
RC2  -  [R_0402]  164.64 55.55 90 bottom
RC3  -  [R_0402]  160.46 50.52 180 top
RC4  -  [R0402_0OHM]  154.42 58.34 270 bottom
RC5  -  [R_0402]  153.2 56.55 0 bottom
RC6  -  [R_0402]  56.81 57.53 90 bottom
RC7  -  [R_0402]  147.29 54.95 180 top
RC8  -  [R_0402]  56.82 56.44 270 bottom
RC9  -  [R_0402]  158.05 48.36 180 top
RC10  -  [R_0402]  78.23 69.38 180 bottom
RC11  -  [R_0402]  157.76 74.5 0 bottom
RC12  -  [R_0402]  158.17 72.24 0 bottom
RC14  -  [R0402_0OHM]  143.57 88.82 270 bottom
RC16  -  [R0603_0OHM]  80.57 75.75 270 bottom
RC17  -  [R_0402]  80.26 78.41 270 top
RC18  -  [R_0402]  75.37 69.32 180 bottom
RC19  -  [R_0402]  142.68 87.91 90 bottom
RC20  -  [R_0402]  79.3 78.41 270 top
RC22  -  [R_0402]  107.99 67.73 0 bottom
RC23  -  [R_0402]  158.05 49.25 180 top
RC24  -  [R_0402]  147.26 54.01 180 top
RC25  -  [R_0402]  150.18 54.01 180 top
RC26  -  [R_0402]  156.21 50.46 180 top
RC28  -  [R_0402]  163.96 69.38 180 top
RC29  -  [R0402_0OHM]  159.08 67.47 180 top
RC30  -  [R_0402]  164.82 69.38 0 top
RC31  -  [R0402_0OHM]  167.39 66.52 180 top
RC33  -  [R0402_0OHM]  160.78 66.5 180 top
RC34  -  [R_0402]  151.63 55.9 90 top
RC35  -  [R0402_0OHM]  167.39 65.57 180 top
RC36  -  [R_0402]  150.67 56.82 270 top
RC37  -  [R_0402]  161.24 70.14 180 bottom
RC38  -  [R_0402]  159.08 68.43 180 top
RC39  -  [R_0402]  168.96 67.97 180 top
RC40  -  [R0402_0OHM]  137.92 87.03 180 bottom
RC44  -  [R_0402]  138.81 87.92 180 bottom
RC45  -  [R_0402]  135.24 86.4 90 bottom
RC46  -  [R_0402]  129.4 89.69 90 bottom
RC47  -  [R_0402]  130.29 89.69 90 bottom
RC50  -  [R_0402]  146.22 56.79 270 top
RC52  -  [R_0402]  164.14 61.61 270 bottom
RC55  -  [R_0402]  160.43 72.24 0 bottom
RC56  -  [R_0402]  108.56 82.08 180 bottom
RC57  -  [R_0402]  158.67 75.37 180 bottom
RC58  -  [R_0402]  35.62 40.26 0 top
RC61  -  [R_0402]  29.53 35.65 180 top
RC63  -  [R_0402]  31.99 18.15 0 top
RC64  -  [R_0402]  146.91 50.27 0 top
RC65  -  [R0402_0OHM]  140.83 55.04 270 top
RC66  -  [R_0402]  146.91 51.16 0 top
RC67  -  [R_0402]  109.74 18.83 0 top
RC68  -  [R_0402]  113.13 17.44 0 top
RC69  -  [R_0402]  110.69 19.74 90 top
RC71  -  [R_0402]  166.27 67.97 0 top
RC72  -  [R0402_0OHM]  167.82 72.86 90 top
RC73  -  [R_0402]  162.8 55.55 90 bottom
RC74  -  [R_0402]  159.92 67.58 0 top
RC76  -  [R_0402]  170.28 71.6 0 top
RC78  -  [R_0402]  161.85 56.46 270 bottom
RC79  -  [R_0402]  160.9 55.55 90 bottom
RC81  -  [R_0402]  168.5 71.6 0 top
RC82  -  [R_0402]  160.91 69.25 180 bottom
RC83  -  [R_0402]  112.2 16.48 180 top
RC84  -  [R_0402]  156.13 70.28 270 bottom
RC86  -  [R0402_0OHM]  158.17 69.32 0 bottom
RC87  -  [R0402_0OHM]  154.8 70.28 270 bottom
RC88  -  [R0402_0OHM]  163.75 56.46 270 bottom
RC89  -  [R0402_0OHM]  175.58 56.49 180 top
RC90  -  [R0402_0OHM]  175.58 58.29 180 top
RC91  -  [R0402_0OHM]  175.58 59.18 180 top
RC92  -  [R0402_0OHM]  175.58 60.07 180 top
RC93  -  [R0402_0OHM]  162.43 58.52 180 bottom
RC94  -  [R0402_0OHM]  153.4 55.9 90 top
RC95  -  [R_0402]  76.44 70.26 90 bottom
RC96  -  [R_0402]  57.7 63.68 0 top
RC97  -  [R0402_0OHM]  78.22 71.17 270 bottom
RC99  -  [R_0402]  70.49 53.59 180 top
RC101  -  [R_0402]  78.35 78.41 270 top
RC102  -  [R_0402]  69.63 63.22 0 top
RC103  -  [R_0402]  74.47 70.26 90 bottom
RC104  -  [R_0402]  75.43 71.17 270 bottom
RC105  -  [R_0402]  70.98 57.57 180 top
RC106  -  [R_0402]  70.98 56.68 180 top
RC107  -  [R0402_0OHM]  70.55 58.71 180 top
RC108  -  [R0402_0OHM]  70.55 60.55 180 top
RC109  -  [R_0402]  57.7 61.06 0 top
RC110  -  [R0402_0OHM]  70.55 61.44 180 top
RC111  -  [R0402_0OHM]  70.58 64.12 180 top
RC112  -  [R0402_0OHM]  70.58 65.08 180 top
RC113  -  [R_0402]  103.86 88.3 0 bottom
RC114  -  [R_0402]  105.6 91.05 270 bottom
RC115  -  [R_0402]  112 87.97 90 bottom
RC116  -  [R_0402]  168.71 73.77 270 top
RC117  -  [R_0402]  105.65 88.89 270 bottom
RC118  -  [R_0402]  109.59 88.89 270 bottom
RC119  -  [R_0402]  108.64 88.89 270 bottom
RC120  -  [R_0402]  69.27 50.98 270 top
RC122  -  [R_0402]  108.64 90.13 90 bottom
RC123  -  [R_0402]  77.33 71.17 270 bottom
RC124  -  [R_0402]  79.17 71.17 270 bottom
RC125  -  [R_0402]  115.18 56.63 270 top
RC126  -  [R_0402]  134.93 28.44 90 top
RC127  -  [R_0402]  80.12 70.26 90 bottom
RC128  -  [R_0402]  135.82 27.58 270 top
RC129  -  [R_0402]  110.6 56.76 270 top
RC130  -  [R_0402]  133.98 29.35 270 top
RC131  -  [R_0402]  79.16 80.15 0 top
RC132  -  [R_0402]  134.93 27.58 270 top
RC133  -  [R_0402]  109.72 56.76 270 top
RC134  -  [R_0402]  138.3 77.76 180 top
RC135  -  [R0402_0OHM]  77.39 77.49 90 top
RC136  -  [R_0402]  163.3 59.52 270 bottom
RC137  -  [R_0402]  160.43 73.19 0 top
RC139  -  [R_0402]  144.45 88.82 270 bottom
RC140  -  [R_0402]  160.43 75.35 0 top
RC141  -  [R_0402]  145.34 88.82 270 bottom
RC142  -  [R0402_0OHM]  70.61 66.01 180 top
RC143  -  [R_0402]  144.51 88.89 270 top
RC144  -  [R_0402]  68.31 71.74 270 top
RC145  -  [R_0402]  143.56 88.89 270 top
RC147  -  [R_0402]  150.05 88.9 270 bottom
RC149  -  [R_0402]  147.31 88.89 270 bottom
RC151  -  [R_0402]  148.13 90.13 90 bottom
RC152  -  [R_0402]  149.21 90.13 90 bottom
RC153  -  [R_0402]  149.16 88.9 270 bottom
RC154  -  [R_0402]  154.72 75.29 0 top
RC155  -  [R_0402]  148.2 88.89 270 bottom
RC158  -  [R_0402]  151.45 86.96 0 bottom
RC159  -  [R_0402]  141.94 65.75 90 top
RC161  -  [R_0402]  134.35 87.31 270 bottom
RC163  -  [R0402_0OHM]  133.34 88.38 270 bottom
RC166  -  [R_0402]  157.07 54.7 270 top
RC168  -  [R_0402]  144.2 56.76 270 bottom
RC169  -  [R_0402]  159.08 73.19 180 bottom
RC170  -  [R_0402]  160.43 73.19 0 bottom
RC172  -  [R0402_0OHM]  110.99 88.89 270 bottom
RC173  -  [R_0402]  56.07 28.3 180 top
RC174  -  [R0402_0OHM]  155.5 78.08 0 top
RC176  -  [R0402_0OHM]  162.87 79.25 270 top
RC178  -  [R_0402]  164.85 75.6 180 top
RC180  -  [R_0402]  121.49 105.79 90 top
RC181  -  [R_0402]  122.43 106.72 270 top
RC185  -  [R_0402]  159.08 78.33 180 bottom
RC189  -  [R_0402]  160.43 77.38 0 top
RC190  -  [R_0402]  159.07 69.42 180 top
RC191  -  [R_0402]  159.08 76.36 180 top
RC193  -  [R_0402]  160.43 76.36 0 top
RC195  -  [R_0402]  52.51 27.47 180 top
RC197  -  [R_0402]  166.54 63.66 0 top
RC199  -  [R_0402]  161.34 74.21 180 top
RC200  -  [R_0402]  149.8 56.82 270 top
RC201  -  [R_0402]  159.08 77.38 180 top
RC202  -  [R_0402]  159.08 77.38 180 bottom
RC203  -  [R_0402]  160.43 78.33 0 top
RC204  -  [R_0402]  161.34 78.13 90 bottom
RC205  -  [R_0402]  145.8 72.01 270 top
RC206  -  [R_0402]  166.47 64.62 0 top
RC208  -  [R_0402]  160.45 78.13 90 bottom
RC210  -  [R_0402]  166.98 61.45 0 top
RC211  -  [R_0402]  88.01 95.99 180 top
RC215  -  [R_0402]  154.66 76.68 0 top
RC216  -  [R_0402]  145.8 72.85 90 top
RC217  -  [R_0402]  55.16 29.25 0 top
RC218  -  [R_0402]  163.93 76.49 0 top
RC221  -  [R_0402]  56.07 27.41 180 top
RC222  -  [R_0402]  160.43 74.21 0 bottom
RC232  -  [R_0402]  108.9 70.21 180 bottom
RC233  -  [R_0402]  108.9 71.09 180 bottom
RC235  -  [R_0402]  108 66.83 0 bottom
RC236  -  [R_0402]  141.81 88.82 270 bottom
RC237  -  [R_0402]  143.31 56.76 270 bottom
RC238  -  [R_0402]  108.57 56.76 270 top
RC239  -  [R_0402]  103.68 56.06 270 top
RC240  -  [R_0402]  108.9 73.76 180 bottom
RC241  -  [R_0402]  108.9 72.87 180 bottom
RC242  -  [R_0603]  114.67 88.11 90 bottom
RC243  -  [R_0402]  110.92 93.78 270 top
RC244  -  [R_0402]  107.43 77.39 270 bottom
RC245  -  [R0402_0OHM]  111.87 93.78 270 top
RC246  -  [R0402_0OHM]  107.29 87.71 270 top
RC247  -  [R0402_0OHM]  112.95 88.89 270 bottom
RC248  -  [R_0402]  109.22 76.49 180 bottom
RC249  -  [R_0402]  108.31 77.38 0 bottom
RC250  -  [R_0402]  111.95 86.84 180 top
RC253  -  [R_0402]  107.62 91.05 270 bottom
RC254  -  [R_0402]  150.94 88.34 0 bottom
RC255  -  [R_0402]  105.88 88.84 90 top
RC256  -  [R_0402]  107.79 89.75 270 top
RC258  -  [R_0402]  107.62 88.89 270 bottom
RC259  -  [R_0402]  106.83 88.84 90 top
RC260  -  [R_0402]  109.79 86.84 180 top
RC261  -  [R0402_0OHM]  166.69 66.2 180 bottom
RC262  -  [R0805_0OHM]  146.66 88.66 270 top
RC263  -  [R0402_0OHM]  107 94.14 180 top
RC264  -  [R_0402]  166.69 65.32 180 bottom
RC265  -  [R_0402]  145.78 70.22 270 top
RC266  -  [R_0402]  111.62 87.05 270 bottom
RC267  -  [R0402_0OHM]  166.54 62.78 0 top
RC268  -  [R_0402]  154.42 60.12 270 bottom
RC269  -  [R_0402]  109.45 55.6 0 bottom
RC272  -  [R_0402]  143.42 69.89 0 top
RC275  -  [R_0402]  139.37 55.9 90 top
RC276  -  [R_0603]  137.91 92.68 270 top
RC279  -  [R0402_0OHM]  76.38 17.74 90 top
RC280  -  [R_0402]  57.7 62.8 0 top
RC282  -  [R_0402]  161.66 79.35 180 top
RC283  -  [R_0402]  155.18 88.92 90 top
RC284  -  [R_0402]  159.08 78.33 180 top
RC285  -  [R_0402]  153.04 86.04 180 bottom
RC287  -  [R_0402]  166.22 76.49 0 top
RC288  -  [R_0402]  154.31 90.4 180 top
RC289  -  [R_0402]  155.11 87.91 0 bottom
RC292  -  [R_0402]  154.72 74.27 0 top
RC295  -  [R_0402]  160.44 77.25 0 bottom
RC300  -  [R0402_0OHM]  175.58 57.38 180 top
RC301  -  [R0402_0OHM]  166.88 55.55 90 bottom
RD1  -  [R0402_0OHM]  57.68 27.38 0 top
RD3  -  [R_0402]  80.58 18.07 180 top
RD5  -  [R0402_0OHM]  119.62 26.34 270 top
RD6  -  [R0402_0OHM]  118.73 26.34 270 top
RD7  -  [R0402_0OHM]  133.98 27.58 270 top
RD10  -  [R0402_0OHM]  198.23 26.53 270 top
RD11  -  [R0402_0OHM]  197.28 26.53 270 top
RD12  -  [R0402_0OHM]  114.05 18.39 180 top
RD13  -  [R0402_0OHM]  112.2 20.21 270 top
RE4  -  [R_0402]  134.53 97.14 270 bottom
RE5  -  [R_0402]  132.26 97.14 270 bottom
RP1  -  [RP_0804_8P4R]  8.98 6.2 270 top
RP2  -  [RP_0804_8P4R]  158.78 73.79 180 top
RP3  -  [RP_0804_8P4R]  15.92 19.84 0 top
RP4  -  [RP_0804_8P4R]  166.83 79.31 180 bottom
RP5  -  [RP_0804_8P4R]  159.97 67.88 180 bottom
RP6  -  [RP_0804_8P4R]  158.78 70.81 180 top
RP7  -  [RP_0804_8P4R]  160.44 70.81 0 top
RP8  -  [RP_0804_8P4R]  166.83 77.82 180 top
RP9  -  [RP_0804_8P4R]  164.63 66.24 180 top
RP10  -  [RP_0804_8P4R]  154.49 55.25 90 top
RP11  -  [RP_0804_8P4R]  11.39 37.96 0 top
ST1  -  [CLIP_C5P1]  77.2 80.1 180 bottom
ST2  -  [H_2P8]  172 63.65 180 bottom
SW1  -  [SW_SKRBAAE010_4P]  224.81 106.4 270 top
T1  -  [TPC12]  143.74 75.98 0 top
T2  -  [TPC12]  144.81 75.26 0 top
T3  -  [TPC12]  143.38 63.83 0 top
T4  -  [TPC12]  154.61 70.97 0 top
T5  -  [TPC12]  151.02 61.98 0 top
T6  -  [TPC12]  139.89 76.42 0 top
T7  -  [TPC12]  137.4 76.11 0 top
T10  -  [TPC12]  155.88 71.14 0 top
T11  -  [TPC12]  158.28 54.53 0 top
T12  -  [TPC12]  155.77 66.89 0 top
T13  -  [TPC12]  155.46 69.93 0 top
T14  -  [TPC12]  145.48 65.04 0 top
T15  -  [TPC12]  145.83 66.43 0 top
T16  -  [TPC12]  140.69 86.87 0 top
T17  -  [TPC12]  140.73 88.21 0 top
T18  -  [TPC12]  139.83 68.21 0 top
T19  -  [TPC12]  138.79 70.55 0 top
T20  -  [TPC12]  108.74 57.95 180 bottom
T21  -  [TPC12]  109.53 59.22 180 bottom
T22  -  [TPC12]  109.94 87.03 180 bottom
T23  -  [TPC12]  110.6 85.89 180 bottom
T24  -  [TPC12]  125.53 85.2 180 bottom
T25  -  [TPC12]  121.08 85.85 180 bottom
T26  -  [TPC12]  120.96 87.22 180 bottom
T27  -  [TPC12]  109.65 75.79 180 bottom
T28  -  [TPC12]  121.08 89.32 180 bottom
T29  -  [TPC12]  136.12 72.58 0 top
T30  -  [TPC12]  136.28 71.25 0 top
T31  -  [TPC12]  110.03 57.19 180 bottom
T32  -  [TPC12]  115.56 87.03 180 bottom
T33  -  [TPC12]  149.61 85.83 180 bottom
T34  -  [TPC12]  139.87 74.51 0 top
T35  -  [TPC12]  154.11 82.5 180 bottom
T36  -  [TPC12]  139.79 73.16 0 top
T37  -  [TPC12]  154.2 81.23 180 bottom
T38  -  [TPC12]  140.13 77.99 0 top
T39  -  [TPC12]  140.22 79.36 0 top
T40  -  [TPC12]  192.86 73.71 0 top
T48  -  [TPC12]  136.07 75.72 0 top
T49  -  [TPC12]  136.2 74.32 0 top
T50  -  [TPC12]  154.19 62.43 180 bottom
T51  -  [TPC12]  137.21 73.44 0 top
T52  -  [TPC12]  123.75 58.01 180 bottom
T53  -  [TPC12]  144.41 74.04 0 top
T54  -  [TPC12]  125.08 56.27 180 bottom
T55  -  [TPC12]  142.06 86.83 0 top
T56  -  [TPC12]  154.9 65.52 180 bottom
T57  -  [TPC12]  143.14 56.54 0 top
T58  -  [TPC12]  137.49 87.05 0 top
T59  -  [TPC12]  147.24 56.81 0 top
T60  -  [TPC12]  138.95 79.49 90 top
T61  -  [TPC12]  143.92 55.1 90 top
T62  -  [TPC12]  138.6 76.66 0 top
T63  -  [TPC12]  143.07 57.66 180 bottom
T64  -  [TPC12]  145.07 57.34 180 bottom
T65  -  [TPC12]  145.02 56.04 180 bottom
T66  -  [TPC12]  119.66 89.79 180 bottom
T67  -  [TPC12]  121.72 91.6 180 bottom
T68  -  [TPC12]  122.43 89.26 180 bottom
T69  -  [TPC12]  118.03 71.6 0 top
T70  -  [TPC12]  134.65 71.06 0 top
T71  -  [TPC12]  137.45 70.6 0 top
T72  -  [TPC12]  138.04 71.97 0 top
T73  -  [TPC12]  104.91 56.22 0 top
T74  -  [TPC12]  109.4 74.46 180 bottom
T75  -  [TPC12]  109.4 74.97 180 bottom
T76  -  [TPC12]  122.29 87.73 180 bottom
T77  -  [TPC12]  116.95 88.94 180 bottom
T78  -  [TPC12]  122.91 86.44 180 bottom
T79  -  [TPC12]  118 68.92 0 top
T80  -  [TPC12]  106.86 55.89 0 top
T81  -  [TPC12]  107.45 57.06 0 top
T82  -  [TPC12]  117.91 70.33 0 top
T83  -  [TPC12]  102.16 56.78 0 top
T84  -  [TPC12]  105.99 56.93 0 top
T85  -  [TPC12]  123.81 87.76 180 bottom
T86  -  [TPC12]  118.05 73.05 0 top
T87  -  [TPC12]  249.81 9.11 0 top
T88  -  [TPC12]  249.97 7.73 0 top
T89  -  [TPC12]  253.5 7.84 0 top
T92  -  [TPC12]  247.83 77 90 top
T93  -  [TPC12]  247.83 75.67 90 top
T94  -  [TAIMA_IH-115-F_24P]  259.83 84.51 180 bottom
T97  -  [TPC12]  16.79 40.49 180 bottom
T98  -  [TPC12]  15.42 39.88 180 bottom
T100  -  [TPC12]  20.69 25.31 0 top
T101  -  [TPC12]  18.83 27.2 0 top
T106  -  [TPC12]  28.91 39.79 180 bottom
T107  -  [TPC12]  26.21 26.07 0 top
T110  -  [TPC12]  26.77 24.88 0 top
T115  -  [TPC12]  14.21 27.61 0 top
T118  -  [TPC12]  12.2 31.69 0 top
T121  -  [TPC12]  26.06 27.48 0 top
T122  -  [TPC12]  108.13 79.1 180 bottom
T123  -  [TPC12]  31.28 20.95 0 top
T126  -  [TPC12]  109.59 78.84 180 bottom
T129  -  [TPC12]  122.8 90.72 180 bottom
T130  -  [TPC12]  109.21 80.11 180 bottom
T131  -  [TPC12]  118.16 89.62 180 bottom
T132  -  [TPC12]  120.38 91.22 180 bottom
T137  -  [TPC12]  154.17 64.43 180 bottom
T138  -  [TPC12]  154.93 67.98 0 top
T139  -  [TPC12]  154.65 74.62 180 bottom
T140  -  [TPC12]  153.44 72.81 180 bottom
T141  -  [TPC12]  154.66 72.9 0 top
U1  -  [W25Q64FVSSIQ_SO8]  168.57 84.68 90 bottom
U2  -  [W25Q32FVSSIQ_SO8]  168.64 67.92 90 bottom
U3  -  [TPS22966DPUR_SON14_2X3]  201.95 24.88 0 top
U5  -  [74AUP1G07GW_TSSOP5]  125.51 24.1 0 top
U6  -  [IDTVMM2320BKG8_BGA_168P-NH]  191.46 84.8 0 top
U7  -  [W25X10BVSNIG_SO8]  187 86.44 0 bottom
U9  -  [APL3512ABI-TRG_SOT23-5]  52.51 69.37 90 top
U11  -  [PI3C3125LEX_TSSOP14]  203.24 82.87 90 bottom
U13  -  [PI3C3125LEX_TSSOP14]  181.55 86.88 0 bottom
U17  -  [ALC3226-CG_QFN48_7X7]  270.58 30.27 0 top
U18  -  [TPS22966DPUR_SON14_2X3]  266.95 19.97 270 top
U19  -  [PI3VDP12412ZHEX_TQFN42_9X3P5]  176.14 88.44 180 top
U20  -  [TC7SH08FU_SSOP5]  245.39 70.81 0 top
U21  -  [WGI218LM-QQ89-B0_QFN48_6X6]  255.5 75.37 90 top
U22  -  [TPS22966DPUR_SON14_2X3]  200.26 39.21 270 top
U23  -  [PI3L720ZHEX_TQFN42_9X3P5]  228.41 102.59 270 bottom
U24  -  [TC7SH08FU_SSOP5]  245.35 82.99 90 top
U25  -  [AT97SC3204-X2A14-AB_TSSOP28]  35.32 30.73 0 top
U26  -  [TC7SH08FU_SSOP5]  252.53 29.45 270 top
U27  -  [OZ777FJ2LN_QFN48_6X6]  260.19 22.95 180 top
U29  -  [TC7SH08FU_SSOP5]  248 13.32 270 top
U30  -  [TC7SH08FU_SSOP5]  191.63 41.81 270 top
U31  -  [TPS22966DPUR_SON14_2X3]  197.72 71.42 180 bottom
U32  -  [G547I2P81U_MSOP8]  229.95 88.33 270 bottom
U33  -  [PI3USB3102ZLEX_TQFN32_6X3]  165.94 105.3 180 top
U35  -  [G547I2P81U_MSOP8]  101.55 102.82 90 top
U36  -  [NX3DV221GM_XQFN10U10_2X1P55]  78.3 83.58 180 top
U37  -  [ECE5048-LZY_DQFN132_11X11]  16.43 29.07 0 top
U38  -  [MEC5075-LZY_DQFN132_11X11]  20.94 9.13 0 top
U39  -  [SLG55594AVTR_TDFN8_2X2]  74.4 87.12 180 top
U41  -  [RT9818A-44GU3_SC70-3]  37.96 17.41 0 top
U42  -  [TC7SH08FU_SSOP5]  41.34 12.74 180 top
U43  -  [TPS22966DPUR_SON14_2X3]  207.12 74.41 0 bottom
U45  -  [TPS22966DPUR_SON14_2X3]  193.49 31.67 90 top
U46  -  [TPS22966DPUR_SON14_2X3]  186.99 66.44 0 top
U47  -  [TC7SH08FU_SSOP5]  13.52 41.39 90 top
U48  -  [AP2330W-7_SC59-3]  184.71 97.14 0 bottom
U49  -  [PI3C3125LEX_TSSOP14]  228.99 89.81 270 top
U50  -  [AP2330W-7_SC59-3]  269.35 83.62 180 top
U52  -  [G547I2P81U_MSOP8]  228.98 83.98 270 top
UC1  -  [HASWELL-MCP-E-ULT_BGA_1168P-T]  151.27 82.81 0 bottom
